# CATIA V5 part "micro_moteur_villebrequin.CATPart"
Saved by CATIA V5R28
Part number: Part7
Bounding box of the stored display mesh (mm): x -20 to 20, y -5.432 to 65, z -20 to 20
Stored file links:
  D:\SAVE\Mécanique\Cotation ISO\Cotation GPS Exercices\Exo 1 ISO GPS\exo1_gps.CATPart
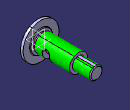
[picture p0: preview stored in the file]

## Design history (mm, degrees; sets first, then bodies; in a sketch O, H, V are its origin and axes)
Body1 (main body)
  Sketch1 on yz-plane, origin (0, 0, 0), H (0, 1, 0), V (0, 0, 1)
    axis line L1 (-165.0541, 0) -> (194.7306, 0)
    point P1 (-165.0541, 0)
    point P3 (0, 0)
    line L2 (0, 0) -> (0, 20)
    line L3 (0, 20) -> (3, 20)
    line L4 (3, 20) -> (3, 12.7)
    line L5 (3.7, 9) -> (5.7, 9)
    line L6 (5.7, 9) -> (5.7, 10)
    line L7 (5.7, 10) -> (45, 10)
    line L8 (45, 10) -> (45, 7)
    line L9 (45, 7) -> (65, 7)
    line L10 (65, 7) -> (65, 0)
    point P12 (65, 0)
    line L11 (3, 12.7) -> (3.7, 12)
    line L12 (3.7, 12) -> (3.7, 9)
    distance L3 L1 = 20
    distance L5 L1 = 9
    length L3 = 3
    distance L7 L1 = 10
    distance L9 L1 = 7
    length L9 = 20
    distance L10 L2 = 65
    length L5 = 2
    distance L12 L4 = 0.7
    angle L11 L4 = 135
    length L12 = 3
    coincidence: P1 H, P3 V, P12 L1, P3 L1
    horizontal: L1 H, L3 H, L5 H, L7 H, L9 H
    vertical: L2 V, L4 V, L6 V, L8 V, L10 V, L12 V
  Shaft1: profile Sketch1, axis Sketch1.L1, angle 360
  Sketch2 on yz-plane, origin (0, 0, 0), H (0, 1, 0), V (0, 0, 1)
    axis line L1 (-16.7434, -14) -> (14.1904, -14)
    point P3 (-5.4324, -14)
    line L2 (-5.4324, -14) -> (-5.4324, -11)
    line L3 (-5.4324, -11) -> (-0.4324, -11)
    line L4 (-0.4324, -11) -> (-0.4324, -10.1124)
    line L5 (-0.4324, -10.1124) -> (0, -9.68)
    point P7 (0, -9.68)
    distance L1 H = 14
    distance L3 L1 = 3
    length L3 = 5
    distance L2 V = 5.4324
    length L4 = 0.8876
    angle L4 L5 = 45
    horizontal: L1 H, L3 H
    coincidence: P3 L1, P7 V
    vertical: L2 V, L4 V
  Shaft2: profile Sketch2, axis Sketch2.L1, angle 360
  Chamfer1: length 1, angle 45, on edge [face of Shaft1 from Sketch1.L9 | face of Shaft1 from Sketch1.L10]
  Chamfer2: length 0.5, angle 45, on edge [face of Shaft2 from Sketch2.L2 | face of Shaft2 from Sketch2.L3]
  Sketch3 on yz-plane, origin (0, 0, 0), H (0, 1, 0), V (0, 0, 1)
    line L1 (69.1705, 17.7117) -> (45, 17.7117)
    line L2 (45, 17.7117) -> (45, 6.796)
    line L3 (45, 6.796) -> (69.1705, 6.796)
    line L4 (69.1705, 6.796) -> (69.1705, 17.7117)
    reference projected line E1 (45, 10) -> (45, -10) from edge [face of Shaft1 from Sketch1.L7 | face of Shaft1 from Sketch1.L8]
    horizontal: L1 H, L3 H
    vertical: L2 V, L4 V
    coincidence: L2 E1
  Pocket1: profile Sketch3, direction (-1, 0, 0), length 20, mirrored extent
  Body2
    Sketch4 on xy-plane, origin (0, 0, 0), H (1, 0, 0), V (0, 1, 0)
      axis line L1 (26.8, 18.3326) -> (-24.0418, 18.3326)
      arc A1 centre (5.8743, 18.3326) radius 4 from (5.8743, 22.3326) to (1.8743, 18.3326) ccw
      point P3 (5.8743, 18.3326)
      point P4 (5.8743, 22.3326)
      line L2 (5.8743, 22.3326) -> (19.2753, 22.3326)
      line L3 (19.2753, 22.3326) -> (19.2753, 18.3326)
      point P6 (5.8743, 22.3326)
      point P7 (1.8743, 18.3326)
      point P8 (19.2753, 18.3326)
      radius A1 = 4
      horizontal: L1 H, L2 H
      coincidence: P3 L1, P4 A1, L2 P6, L1 P7, L1 P8
      vertical: L3 V
      tangency: L2 A1
    Revol1: Element1 Sketch4, Angle1 0
    Plane1: type Normal, Curve Sketch4.L3, RefPoint Sketch4.P8, Ratio 0
    Symmetry1: Reference Plane1, ToTransfor Revol1
    Join1: Elements (Revol1; Symmetry1)
    Boundary1: Boundary Join1
    Sketch5 on Plane1, origin (0, 18.3326, 0), H (-1, 0, 0), V (0, 0, 1)
      arc A1 centre (0, 0) radius 6.8769 from (-6.8769, 0) to (6.8769, 0) ccw
      axis line L1 (-28.4034, 0) -> (28.7913, 0)
      point P1 (-28.4034, 0)
      point P3 (-6.8769, 0)
      point P4 (6.8769, 0)
      coincidence: P1 H, L1 P4, L1 P3
      horizontal: L1 H
    Sweep1: type Unspec, Profile Boundary1, Guide Sketch5
    Symmetry2: Reference yz-plane, ToTransfor Join1
    Join2: Elements (Symmetry2; Sweep1; Join1)
    CloseSurface1: CloseElement Join2
  Remove1: tool Body2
